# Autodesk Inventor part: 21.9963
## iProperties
Created: 2012-06
Part Number: 21.9963
Document SubType Name: Modeling
Designer: Administrator
Density: 7.85 g/cm^3
Material: Steel
Description: M6X12 BUTTON HEAD FLANGE
Vendor: S
Mass: 4.08587 g
Surface Area: 7.32367 cm^2
Volume: 0.520493 cm^3
Translation Standard: STEP AP203
FileName: 92137A527.step
PreProcessor: SolidWorks 2006233
PostProcessor: Build: 236a, Release: 2009 RTM - Date: Fri 02/22/2008
Sent Units: MM
Uncertainty: 1e-05
Author: Administrator
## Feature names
1. Base1
